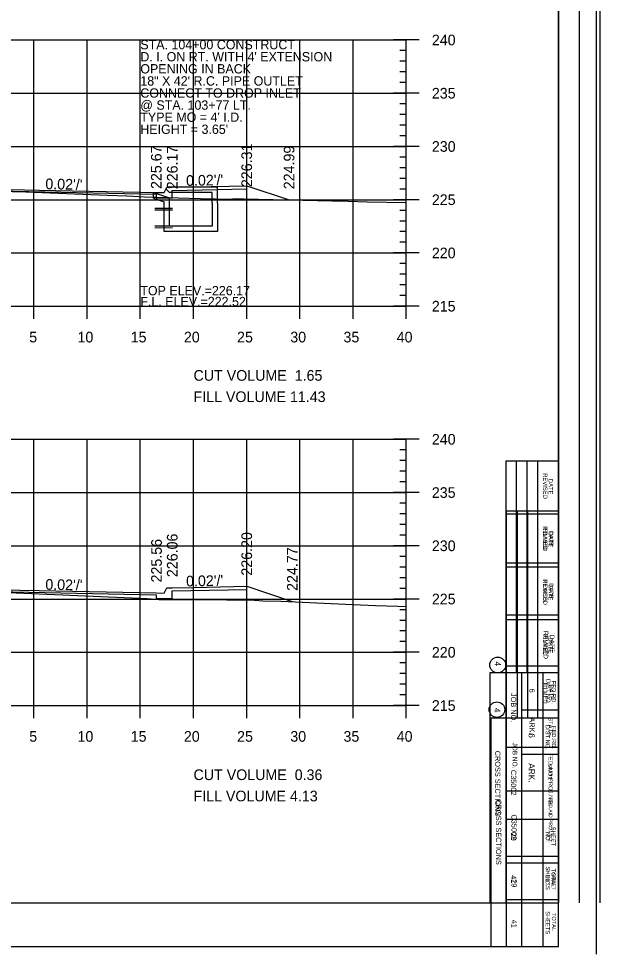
# Model space of a CAD drawing. Extents: x 1367903 to 1373764, y 376865 to 382130.
# Drawn here: x 1370800 to 1370909.3, y 377279.1 to 377454.8 of the extents above; entities that cross this region are included whole.
import ezdxf

# ---------------------------------------------------------------- set-up
doc = ezdxf.new("R2010")
doc.units = 0
for name, color, linetype in [('R_Axis', 7, 'Continuous'), ('R_Axis Annot', 7, 'Continuous'), ('R_Border', 7, 'Continuous'), ('R_Border Notes', 7, 'Continuous'), ('R_Border PE', 7, 'Continuous'), ('R_Draft', 7, 'Continuous'), ('R_Exist Surface', 7, 'Continuous'), ('R_Fin Surface', 7, 'Continuous'), ('R_Fin Surface Annot', 7, 'Continuous'), ('R_Grid', 7, 'Continuous'), ('R_Water', 7, 'Continuous'), ('R_Water Annot', 7, 'Continuous')]:
    doc.layers.add(name, color=color, linetype=linetype)

msp = doc.modelspace()

# ---------------------------------------------------------------- linework, layer by layer
for p, q in [((1370827.7, 377422.85), (1370827.87, 377423.18)), ((1370827.7, 377422.85), (1370828.37, 377422.18)), ((1370837.37, 377423.18), (1370827.87, 377423.18)), ((1370837.37, 377420.18), (1370837.37, 377423.18)), ((1370825.37, 377422.22), (1370828.37, 377421.18)), ((1370825.37, 377421.16), (1370827.37, 377420.47)), ((1370836.37, 377422.18), (1370828.37, 377422.18)), ((1370828.37, 377420.18), (1370828.37, 377421.18)), ((1370836.37, 377420.18), (1370836.37, 377422.18)), ((1370827.37, 377420.18), (1370827.37, 377420.47))]:
    msp.add_line(p, q)
for points in [[(1370756.87, 377423.18), (1370756.87, 377422.52), (1370756.87, 377422.52), (1370756.87, 377421.15), (1370759.87, 377421.21), (1370759.87, 377421.88), (1370792.87, 377422.54), (1370825.87, 377421.88), (1370825.87, 377421.21), (1370828.87, 377421.15), (1370828.87, 377422.6), (1370842.87, 377422.88), (1370842.87, 377423.46)], [(1370825.37, 377421.16), (1370825.37, 377422.22)], [(1370756.87, 377347.95), (1370756.87, 377347.28), (1370756.87, 377347.28), (1370756.87, 377345.92), (1370759.87, 377345.98), (1370759.87, 377346.65), (1370792.87, 377347.31), (1370825.87, 377346.65), (1370825.87, 377345.98), (1370828.87, 377345.92), (1370828.87, 377347.36), (1370842.87, 377347.64), (1370842.87, 377348.23)]]:
    msp.add_lwpolyline(points)
at = {"layer": 'R_Axis'}
for p, q in [((1370875.27, 377450.84), (1370870.47, 377450.84)), ((1370872.87, 377400.84), (1370872.87, 377450.84)), ((1370872.87, 377448.84), (1370871.67, 377448.84)), ((1370872.87, 377446.84), (1370871.67, 377446.84)), ((1370872.87, 377444.84), (1370871.67, 377444.84)), ((1370872.87, 377442.84), (1370871.67, 377442.84)), ((1370875.27, 377440.84), (1370870.47, 377440.84)), ((1370872.87, 377438.84), (1370871.67, 377438.84)), ((1370872.87, 377436.84), (1370871.67, 377436.84)), ((1370872.87, 377434.84), (1370871.67, 377434.84)), ((1370872.87, 377432.84), (1370871.67, 377432.84)), ((1370875.27, 377430.84), (1370870.47, 377430.84)), ((1370872.87, 377428.84), (1370871.67, 377428.84)), ((1370872.87, 377426.84), (1370871.67, 377426.84)), ((1370872.87, 377424.84), (1370871.67, 377424.84)), ((1370872.87, 377422.84), (1370871.67, 377422.84)), ((1370875.27, 377420.84), (1370870.47, 377420.84)), ((1370872.87, 377418.84), (1370871.67, 377418.84)), ((1370872.87, 377416.84), (1370871.67, 377416.84)), ((1370872.87, 377414.84), (1370871.67, 377414.84)), ((1370872.87, 377412.84), (1370871.67, 377412.84)), ((1370875.27, 377410.84), (1370870.47, 377410.84)), ((1370872.87, 377408.84), (1370871.67, 377408.84)), ((1370872.87, 377406.84), (1370871.67, 377406.84)), ((1370872.87, 377404.84), (1370871.67, 377404.84)), ((1370802.87, 377398.44), (1370802.87, 377403.24)), ((1370812.87, 377398.44), (1370812.87, 377403.24)), ((1370822.87, 377398.44), (1370822.87, 377403.24)), ((1370832.87, 377398.44), (1370832.87, 377403.24)), ((1370842.87, 377398.44), (1370842.87, 377403.24)), ((1370852.87, 377398.44), (1370852.87, 377403.24)), ((1370862.87, 377398.44), (1370862.87, 377403.24)), ((1370872.87, 377402.84), (1370871.67, 377402.84)), ((1370872.87, 377398.44), (1370872.87, 377403.24)), ((1370712.87, 377400.84), (1370872.87, 377400.84)), ((1370875.27, 377400.84), (1370870.47, 377400.84)), ((1370875.27, 377375.84), (1370870.47, 377375.84)), ((1370872.87, 377325.84), (1370872.87, 377375.84)), ((1370872.87, 377373.84), (1370871.67, 377373.84)), ((1370872.87, 377371.84), (1370871.67, 377371.84)), ((1370872.87, 377369.84), (1370871.67, 377369.84)), ((1370872.87, 377367.84), (1370871.67, 377367.84)), ((1370875.27, 377365.84), (1370870.47, 377365.84)), ((1370872.87, 377363.84), (1370871.67, 377363.84)), ((1370872.87, 377361.84), (1370871.67, 377361.84)), ((1370872.87, 377359.84), (1370871.67, 377359.84)), ((1370872.87, 377357.84), (1370871.67, 377357.84)), ((1370875.27, 377355.84), (1370870.47, 377355.84)), ((1370872.87, 377353.84), (1370871.67, 377353.84)), ((1370872.87, 377351.84), (1370871.67, 377351.84)), ((1370872.87, 377349.84), (1370871.67, 377349.84)), ((1370872.87, 377347.84), (1370871.67, 377347.84)), ((1370875.27, 377345.84), (1370870.47, 377345.84)), ((1370872.87, 377343.84), (1370871.67, 377343.84)), ((1370872.87, 377341.84), (1370871.67, 377341.84)), ((1370872.87, 377339.84), (1370871.67, 377339.84)), ((1370872.87, 377337.84), (1370871.67, 377337.84)), ((1370875.27, 377335.84), (1370870.47, 377335.84)), ((1370872.87, 377333.84), (1370871.67, 377333.84)), ((1370872.87, 377331.84), (1370871.67, 377331.84)), ((1370872.87, 377329.84), (1370871.67, 377329.84)), ((1370802.87, 377323.44), (1370802.87, 377328.24)), ((1370812.87, 377323.44), (1370812.87, 377328.24)), ((1370822.87, 377323.44), (1370822.87, 377328.24)), ((1370832.87, 377323.44), (1370832.87, 377328.24)), ((1370842.87, 377323.44), (1370842.87, 377328.24)), ((1370852.87, 377323.44), (1370852.87, 377328.24)), ((1370862.87, 377323.44), (1370862.87, 377328.24)), ((1370872.87, 377327.84), (1370871.67, 377327.84)), ((1370872.87, 377323.44), (1370872.87, 377328.24)), ((1370712.87, 377325.84), (1370872.87, 377325.84)), ((1370875.27, 377325.84), (1370870.47, 377325.84))]:
    msp.add_line(p, q, dxfattribs=at)
at = {"layer": 'R_Border'}
for p, q in [((1370908.53, 377620.35), (1370908.53, 377279.12)), ((1370901.49, 377280.59), (1370901.49, 377611.47)), ((1370901.49, 377446.03), (1370901.49, 377446.03)), ((1370891.68, 377280.59), (1370891.68, 377362.43)), ((1370891.68, 377362.43), (1370901.49, 377362.43)), ((1370891.68, 377362.43), (1370893.72, 377362.43)), ((1370893.72, 377362.43), (1370893.72, 377323.46)), ((1370895.66, 377362.43), (1370895.66, 377323.46)), ((1370897.51, 377362.43), (1370897.51, 377323.46)), ((1370891.68, 377352.62), (1370901.3, 377352.62)), ((1370891.68, 377342.9), (1370901.3, 377342.9)), ((1370891.68, 377333.27), (1370901.3, 377333.27)), ((1370901.49, 377323.46), (1370888.76, 377323.46)), ((1370888.76, 377323.46), (1370888.76, 377280.59)), ((1370894.6, 377280.59), (1370894.6, 377323.46)), ((1370898.58, 377280.59), (1370898.58, 377323.46)), ((1370901.49, 377316.65), (1370894.6, 377316.65)), ((1370901.49, 377309.75), (1370891.68, 377309.75)), ((1370901.49, 377296.24), (1370891.68, 377296.24)), ((1370901.49, 377289.33), (1370891.68, 377289.33)), ((1370697.17, 377280.59), (1370901.49, 377280.59))]:
    msp.add_line(p, q, dxfattribs=at)
msp.add_circle((1370889.9, 377325.07), 1.46, dxfattribs=at)
at = {"layer": 'R_Border PE'}
for p, q in [((1370905.42, 377288.8), (1370905.42, 377610.76)), ((1370909.33, 377288.8), (1370909.33, 377610.76)), ((1370901.49, 377603.25), (1370901.49, 377288.8)), ((1370891.55, 377371.74), (1370891.55, 377288.8)), ((1370901.49, 377371.74), (1370891.55, 377371.74)), ((1370893.54, 377371.74), (1370893.54, 377331.96)), ((1370895.52, 377371.74), (1370895.52, 377331.96)), ((1370897.51, 377371.74), (1370897.51, 377331.96)), ((1370901.49, 377361.8), (1370891.55, 377361.8)), ((1370901.49, 377351.85), (1370891.55, 377351.85)), ((1370901.49, 377341.91), (1370891.55, 377341.91)), ((1370901.49, 377331.96), (1370888.56, 377331.96)), ((1370888.56, 377331.96), (1370888.56, 377288.8)), ((1370894.53, 377331.96), (1370894.53, 377288.8)), ((1370898.51, 377331.96), (1370898.51, 377288.8)), ((1370894.59, 377325), (1370901.49, 377325)), ((1370891.68, 377318.04), (1370901.49, 377318.04)), ((1370891.68, 377304.51), (1370901.49, 377304.51)), ((1370891.68, 377297.55), (1370901.49, 377297.55)), ((1370697.17, 377288.8), (1370901.49, 377288.8)), ((1370898.6, 377288.8), (1370898.6, 377288.8))]:
    msp.add_line(p, q, dxfattribs=at)
msp.add_circle((1370890.05, 377333.45), 1.49, dxfattribs=at)
at = {"layer": 'R_Exist Surface'}
for points in [[(1370793.72, 377422.5), (1370801.33, 377422.29), (1370816.66, 377421.71), (1370820.36, 377421.59), (1370823.64, 377421.37), (1370825.2, 377421.33), (1370825.81, 377421.31), (1370834.17, 377421.08), (1370839.79, 377420.96), (1370840.22, 377420.98), (1370842.33, 377420.98), (1370858.96, 377420.65), (1370861.08, 377420.61), (1370861.92, 377420.59), (1370865.48, 377420.45), (1370872.87, 377420.33)], [(1370712.87, 377349.87), (1370732.39, 377349.96), (1370740.51, 377350.07), (1370746.45, 377348.41), (1370751.41, 377346.59), (1370754.74, 377345.36), (1370757.1, 377344.61), (1370760.4, 377345.52), (1370764.25, 377346.84), (1370764.41, 377346.88), (1370765.86, 377347.14), (1370789.45, 377347.26), (1370794.18, 377347.28), (1370799.52, 377347.03), (1370824.15, 377345.97), (1370826.34, 377345.73), (1370839.08, 377345.71), (1370843.6, 377345.67), (1370845.88, 377345.51), (1370849.36, 377345.47), (1370861.41, 377344.89), (1370867.07, 377344.65), (1370871.28, 377344.49), (1370872.87, 377344.43)]]:
    msp.add_lwpolyline(points, dxfattribs=at)
at = {"layer": 'R_Fin Surface'}
for points in [[(1370754.21, 377422.3), (1370756.87, 377423.18), (1370757.87, 377423.18), (1370758.37, 377422.18), (1370759.87, 377422.21), (1370781.87, 377422.65), (1370792.87, 377422.87), (1370803.87, 377422.65), (1370825.87, 377422.21), (1370827.37, 377422.18), (1370827.87, 377423.18), (1370828.87, 377423.18), (1370832.87, 377423.26), (1370842.87, 377423.46), (1370850.83, 377420.81)], [(1370752.06, 377346.35), (1370756.87, 377347.95), (1370757.87, 377347.95), (1370758.37, 377346.95), (1370759.87, 377346.98), (1370781.87, 377347.42), (1370792.87, 377347.64), (1370803.87, 377347.42), (1370825.87, 377346.98), (1370827.37, 377346.95), (1370827.87, 377347.95), (1370828.87, 377347.95), (1370832.87, 377348.03), (1370842.87, 377348.23), (1370851.44, 377345.37)]]:
    msp.add_lwpolyline(points, dxfattribs=at)
at = {"layer": 'R_Grid'}
for p, q in [((1370712.87, 377450.84), (1370872.87, 377450.84)), ((1370802.87, 377400.84), (1370802.87, 377450.84)), ((1370812.87, 377400.84), (1370812.87, 377450.84)), ((1370822.87, 377400.84), (1370822.87, 377450.84)), ((1370832.87, 377400.84), (1370832.87, 377450.84)), ((1370842.87, 377400.84), (1370842.87, 377450.84)), ((1370852.87, 377400.84), (1370852.87, 377450.84)), ((1370862.87, 377400.84), (1370862.87, 377450.84)), ((1370872.87, 377400.84), (1370872.87, 377450.84)), ((1370712.87, 377440.84), (1370872.87, 377440.84)), ((1370712.87, 377430.84), (1370872.87, 377430.84)), ((1370712.87, 377420.84), (1370872.87, 377420.84)), ((1370712.87, 377410.84), (1370872.87, 377410.84)), ((1370712.87, 377400.84), (1370872.87, 377400.84)), ((1370712.87, 377375.84), (1370872.87, 377375.84)), ((1370802.87, 377325.84), (1370802.87, 377375.84)), ((1370812.87, 377325.84), (1370812.87, 377375.84)), ((1370822.87, 377325.84), (1370822.87, 377375.84)), ((1370832.87, 377325.84), (1370832.87, 377375.84)), ((1370842.87, 377325.84), (1370842.87, 377375.84)), ((1370852.87, 377325.84), (1370852.87, 377375.84)), ((1370862.87, 377325.84), (1370862.87, 377375.84)), ((1370872.87, 377325.84), (1370872.87, 377375.84)), ((1370712.87, 377365.84), (1370872.87, 377365.84)), ((1370712.87, 377355.84), (1370872.87, 377355.84)), ((1370712.87, 377345.84), (1370872.87, 377345.84)), ((1370712.87, 377335.84), (1370872.87, 377335.84)), ((1370712.87, 377325.84), (1370872.87, 377325.84))]:
    msp.add_line(p, q, dxfattribs=at)
at = {"layer": 'R_Water'}
for p, q in [((1370828.92, 377419.21), (1370825.58, 377419.19)), ((1370828.92, 377418.88), (1370825.58, 377418.86)), ((1370828.92, 377415.88), (1370825.58, 377415.86)), ((1370828.92, 377415.55), (1370825.58, 377415.52))]:
    msp.add_line(p, q, dxfattribs=at)
for points in [[(1370837.37, 377420.18), (1370837.37, 377414.88), (1370832.37, 377414.88), (1370827.37, 377414.88), (1370827.37, 377420.18)], [(1370836.37, 377420.18), (1370836.37, 377415.88), (1370832.37, 377415.88), (1370828.37, 377415.88), (1370828.37, 377420.18)]]:
    msp.add_lwpolyline(points, dxfattribs=at)

# ---------------------------------------------------------------- texts
at = {"layer": 'R_Axis Annot'}
for s, p in [('240', (1370877.67, 377449.84)), ('235', (1370877.67, 377439.84)), ('230', (1370877.67, 377429.84)), ('225', (1370877.67, 377419.84)), ('220', (1370877.67, 377409.84)), ('215', (1370877.67, 377399.84)), ('5', (1370801.99, 377394.04)), ('10', (1370811.06, 377394.04)), ('15', (1370821.06, 377394.04)), ('20', (1370831.06, 377394.04)), ('25', (1370841.06, 377394.04)), ('30', (1370851.06, 377394.04)), ('35', (1370861.06, 377394.04)), ('40', (1370871.06, 377394.04)), ('CUT VOLUME  1.65', (1370832.87, 377386.84)), ('FILL VOLUME 11.43', (1370832.87, 377382.84)), ('240', (1370877.67, 377374.84)), ('235', (1370877.67, 377364.84)), ('230', (1370877.67, 377354.84)), ('225', (1370877.67, 377344.84)), ('220', (1370877.67, 377334.84)), ('215', (1370877.67, 377324.84)), ('5', (1370801.99, 377319.04)), ('10', (1370811.06, 377319.04)), ('15', (1370821.06, 377319.04)), ('20', (1370831.06, 377319.04)), ('25', (1370841.06, 377319.04)), ('30', (1370851.06, 377319.04)), ('35', (1370861.06, 377319.04)), ('40', (1370871.06, 377319.04)), ('CUT VOLUME  0.36', (1370832.87, 377311.84)), ('FILL VOLUME 4.13', (1370832.87, 377307.84))]:
    msp.add_text(s, height=2, dxfattribs=at).set_placement(p)
at = {"layer": 'R_Border'}
for s, height, p in [('REVISED', 0.778, (1370898.58, 377359.51)), ('DATE', 0.778, (1370899.74, 377358.64)), ('FILMED', 0.778, (1370898.58, 377349.41)), ('DATE', 0.778, (1370899.74, 377348.82)), ('REVISED', 0.875, (1370898.68, 377339.88)), ('DATE', 0.875, (1370899.84, 377339.1)), ('FILMED', 0.778, (1370898.58, 377330.16)), ('DATE', 0.778, (1370899.74, 377329.77)), ('4', 1.17, (1370889.39, 377325.4)), ('DIST.NO.', 0.778, (1370899.07, 377322.19)), ('FED.RD.', 0.778, (1370900.23, 377321.99)), ('6', 1.17, (1370895.85, 377320.63)), ('JOB NO.', 0.875, (1370892.85, 377318.88)), ('ARK.', 1.166, (1370895.85, 377315)), ('STATE', 0.681, (1370899.55, 377314.9)), ('FED.AID PROJ.NO.', 0.6805, (1370899.65, 377308.49)), ('SHEET', 0.681, (1370900.23, 377294.39)), ('NO.', 0.681, (1370899.07, 377293.61)), ('SHEETS', 0.778, (1370899.07, 377287.2)), ('TOTAL', 0.778, (1370900.23, 377286.91))]:
    msp.add_text(s, height=height, rotation=270, dxfattribs=at).set_placement(p)
at = {"layer": 'R_Border Notes'}
for s, height, p in [('CROSS SECTIONS', 0.9945, (1370889.72, 377308.2)), ('C35002', 0.995, (1370892.64, 377305.39)), ('29', 0.995, (1370892.64, 377293.23)), ('41', 0.995, (1370892.64, 377285.62))]:
    msp.add_text(s, height=height, rotation=270, dxfattribs=at).set_placement(p)
at = {"layer": 'R_Border PE'}
for s, height, p in [('REVISED', 0.796, (1370898.59, 377369.47)), ('DATE', 0.796, (1370899.62, 377368.41)), ('FILMED', 0.796, (1370898.59, 377359.12)), ('DATE', 0.796, (1370899.62, 377358.47)), ('REVISED', 0.796, (1370898.59, 377349.57)), ('DATE', 0.796, (1370899.62, 377348.52)), ('FILMED', 0.796, (1370898.59, 377339.23)), ('DATE', 0.796, (1370899.62, 377338.58)), ('4', 1.19, (1370889.46, 377334.12)), ('DIST.NO.', 0.796, (1370899.16, 377330.83)), ('FED.RD.', 0.796, (1370900.19, 377330.52)), ('JOB NO.', 0.995, (1370892.54, 377328.19)), ('6', 0.995, (1370896.02, 377329.02)), ('ARK.', 0.995, (1370896.02, 377323.6)), ('STATE', 0.796, (1370899.6, 377323.66)), ('CROSS SECTIONS', 0.9945, (1370889.56, 377317.35)), ('FED.AID PROJ.NO.', 0.7956, (1370899.6, 377316.88)), ('C35002', 0.995, (1370892.54, 377313.75)), ('29', 0.995, (1370892.54, 377301.96)), ('NO.', 0.796, (1370899.09, 377302.11)), ('SHEET', 0.796, (1370900.12, 377303.09)), ('SHEETS', 0.796, (1370899.09, 377295.62)), ('TOTAL', 0.796, (1370900.12, 377295.23)), ('41', 0.995, (1370892.54, 377293.96))]:
    msp.add_text(s, height=height, rotation=270, dxfattribs=at).set_placement(p)
at = {"layer": 'R_Draft'}
for s, p in [('STA. 104+00 CONSTRUCT', (1370822.87, 377449.09)), ("D. I. ON RT. WITH 4' EXTENSION", (1370822.87, 377446.82)), ('OPENING IN BACK', (1370822.87, 377444.55)), ('18" X 42\' R.C. PIPE OUTLET', (1370822.87, 377442.28)), ('CONNECT TO DROP INLET', (1370822.87, 377440.01)), ('@ STA. 103+77 LT.', (1370822.87, 377437.74)), ("TYPE MO = 4' I.D.", (1370822.87, 377435.47)), ("HEIGHT = 3.65'", (1370822.87, 377433.2))]:
    msp.add_text(s, height=1.75, dxfattribs=at).set_placement(p)
at = {"layer": 'R_Fin Surface Annot'}
for s, rotation, p in [('225.67', 90, (1370826.87, 377422.85)), ('226.17', 90, (1370829.87, 377422.81)), ('226.31', 90, (1370843.87, 377423.2)), ('224.99', 90, (1370851.83, 377422.81)), ("0.02'/'", 358.8542, (1370805, 377422.83)), ("0.02'/'", 1.1458, (1370831.49, 377423.43)), ('226.06', 90, (1370829.87, 377349.95)), ('226.20', 90, (1370843.87, 377350.23)), ('225.56', 90, (1370826.91, 377348.95)), ('224.77', 90, (1370852.44, 377347.37)), ("0.02'/'", 358.8541, (1370805, 377347.6)), ("0.02'/'", 1.1456, (1370831.49, 377348.2))]:
    msp.add_text(s, height=2, rotation=rotation, dxfattribs=at).set_placement(p)
at = {"layer": 'R_Water Annot'}
for s, p in [('TOP ELEV.=226.17', (1370822.87, 377402.89)), ('F.L. ELEV.=222.52', (1370822.87, 377400.84))]:
    msp.add_text(s, height=1.75, dxfattribs=at).set_placement(p)

doc.saveas('drawing.dxf')
